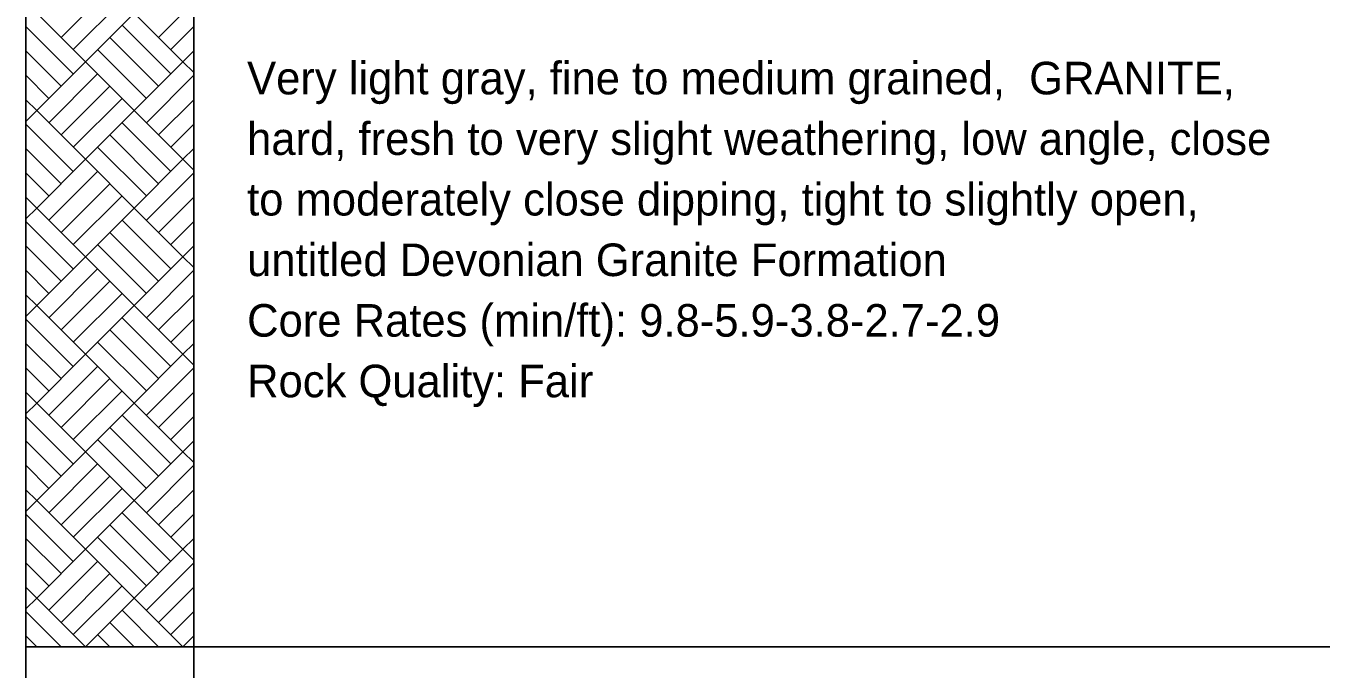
# Model space of a CAD drawing. Extents: x 9422 to 9552, y 6780 to 6860.
# Drawn here: x 9476.15 to 9485.01, y 6805.86 to 6810.26 of the extents above; entities that cross this region are included whole.
import ezdxf

# ---------------------------------------------------------------- set-up
doc = ezdxf.new("R2010")
doc.units = 0
doc.layers.add('7', color=7, linetype='Continuous')
doc.layers.add('8', color=7, linetype='Continuous')

msp = doc.modelspace()

# ---------------------------------------------------------------- linework, layer by layer
at = {"layer": '7'}
for p, q in [((9476.1476, 6811.0107), (9476.1476, 6806.0107)), ((9477.2959, 6806.0107), (9477.2959, 6811.0107)), ((9476.1476, 6806.0107), (9477.2959, 6806.0107))]:
    msp.add_line(p, q, dxfattribs=at)
for points in [[(9476.1476, 6822.0384), (9476.1476, 6796.9829)], [(9477.2959, 6822.0384), (9477.2959, 6796.9829)], [(9477.2959, 6806.0107), (9488.2385, 6806.0107)]]:
    msp.add_lwpolyline(points, dxfattribs=at)
at = {"layer": '8'}
for p, q in [((9476.7218, 6810.5107), (9476.3884, 6810.1773)), ((9476.8051, 6810.4273), (9476.4718, 6810.094)), ((9477.2959, 6810.4182), (9477.0551, 6810.1773)), ((9476.2218, 6810.344), (9476.5551, 6810.0107)), ((9476.8884, 6810.344), (9476.5551, 6810.0107)), ((9476.8884, 6810.344), (9476.5551, 6810.0107)), ((9476.8884, 6810.344), (9477.2218, 6810.0107)), ((9476.1476, 6810.2515), (9476.4718, 6809.9273)), ((9476.8051, 6810.2607), (9477.1384, 6809.9273)), ((9477.2959, 6810.2515), (9477.1384, 6810.094)), ((9476.7218, 6810.1773), (9477.0551, 6809.844)), ((9476.1476, 6810.0848), (9476.3884, 6809.844)), ((9476.6384, 6810.094), (9476.9718, 6809.7607)), ((9477.2959, 6810.0848), (9477.2218, 6810.0107)), ((9477.2959, 6810.0848), (9477.2218, 6810.0107)), ((9476.5551, 6810.0107), (9476.2218, 6809.6773)), ((9476.5551, 6810.0107), (9476.2218, 6809.6773)), ((9476.8884, 6809.6773), (9476.5551, 6810.0107)), ((9476.5551, 6810.0107), (9476.8884, 6809.6773)), ((9477.2218, 6810.0107), (9476.8884, 6809.6773)), ((9477.2218, 6810.0107), (9476.8884, 6809.6773)), ((9477.2959, 6809.9365), (9477.2218, 6810.0107)), ((9477.2218, 6810.0107), (9477.2959, 6809.9365)), ((9476.1476, 6809.9182), (9476.3051, 6809.7607)), ((9476.6384, 6809.9273), (9476.3051, 6809.594)), ((9477.2959, 6809.9182), (9476.9718, 6809.594)), ((9476.7218, 6809.844), (9476.3884, 6809.5107)), ((9476.2218, 6809.6773), (9476.1476, 6809.7515)), ((9476.8051, 6809.7607), (9476.4718, 6809.4273)), ((9477.2959, 6809.7515), (9477.0551, 6809.5107)), ((9476.2218, 6809.6773), (9476.1476, 6809.6032)), ((9476.2218, 6809.6773), (9476.5551, 6809.344)), ((9476.8884, 6809.6773), (9476.5551, 6809.344)), ((9476.8884, 6809.6773), (9476.5551, 6809.344)), ((9476.8884, 6809.6773), (9477.2218, 6809.344)), ((9476.1476, 6809.5848), (9476.4718, 6809.2607)), ((9476.8051, 6809.594), (9477.1384, 6809.2607)), ((9477.2959, 6809.5848), (9477.1384, 6809.4273)), ((9476.7218, 6809.5107), (9477.0551, 6809.1773)), ((9476.1476, 6809.4182), (9476.3884, 6809.1773)), ((9476.5551, 6809.344), (9476.2218, 6809.0107)), ((9476.5551, 6809.344), (9476.2218, 6809.0107)), ((9476.8884, 6809.0107), (9476.5551, 6809.344)), ((9476.5551, 6809.344), (9476.8884, 6809.0107)), ((9476.6384, 6809.4273), (9476.9718, 6809.094)), ((9477.2218, 6809.344), (9476.8884, 6809.0107)), ((9477.2218, 6809.344), (9476.8884, 6809.0107)), ((9477.2959, 6809.4182), (9477.2218, 6809.344)), ((9477.2959, 6809.4182), (9477.2218, 6809.344)), ((9477.2959, 6809.2699), (9477.2218, 6809.344)), ((9477.2218, 6809.344), (9477.2959, 6809.2699)), ((9476.6384, 6809.2607), (9476.3051, 6808.9273)), ((9476.1476, 6809.2515), (9476.3051, 6809.094)), ((9476.7218, 6809.1773), (9476.3884, 6808.844)), ((9477.2959, 6809.2515), (9476.9718, 6808.9273)), ((9476.2218, 6809.0107), (9476.1476, 6809.0848)), ((9476.8051, 6809.094), (9476.4718, 6808.7607)), ((9477.2959, 6809.0848), (9477.0551, 6808.844)), ((9476.2218, 6809.0107), (9476.1476, 6808.9365)), ((9476.2218, 6809.0107), (9476.5551, 6808.6773)), ((9476.8884, 6809.0107), (9476.5551, 6808.6773)), ((9476.8884, 6809.0107), (9476.5551, 6808.6773)), ((9476.8884, 6809.0107), (9477.2218, 6808.6773)), ((9476.1476, 6808.9182), (9476.4718, 6808.594)), ((9476.8051, 6808.9273), (9477.1384, 6808.594)), ((9477.2959, 6808.9182), (9477.1384, 6808.7607)), ((9476.7218, 6808.844), (9477.0551, 6808.5107)), ((9476.1476, 6808.7515), (9476.3884, 6808.5107)), ((9476.6384, 6808.7607), (9476.9718, 6808.4273)), ((9477.2959, 6808.7515), (9477.2218, 6808.6773)), ((9477.2959, 6808.7515), (9477.2218, 6808.6773)), ((9476.5551, 6808.6773), (9476.2218, 6808.344)), ((9476.5551, 6808.6773), (9476.2218, 6808.344)), ((9476.8884, 6808.344), (9476.5551, 6808.6773)), ((9476.5551, 6808.6773), (9476.8884, 6808.344)), ((9477.2218, 6808.6773), (9476.8884, 6808.344)), ((9477.2218, 6808.6773), (9476.8884, 6808.344)), ((9477.2959, 6808.6032), (9477.2218, 6808.6773)), ((9477.2218, 6808.6773), (9477.2959, 6808.6032)), ((9476.1476, 6808.5848), (9476.3051, 6808.4273)), ((9476.6384, 6808.594), (9476.3051, 6808.2607)), ((9477.2959, 6808.5848), (9476.9718, 6808.2607)), ((9476.7218, 6808.5107), (9476.3884, 6808.1773)), ((9476.2218, 6808.344), (9476.1476, 6808.4182)), ((9476.8051, 6808.4273), (9476.4718, 6808.094)), ((9477.2959, 6808.4182), (9477.0551, 6808.1773)), ((9476.2218, 6808.344), (9476.1476, 6808.2699)), ((9476.2218, 6808.344), (9476.5551, 6808.0107)), ((9476.8884, 6808.344), (9476.5551, 6808.0107)), ((9476.8884, 6808.344), (9476.5551, 6808.0107)), ((9476.8884, 6808.344), (9477.2218, 6808.0107)), ((9476.1476, 6808.2515), (9476.4718, 6807.9273)), ((9476.8051, 6808.2607), (9477.1384, 6807.9273)), ((9477.2959, 6808.2515), (9477.1384, 6808.094)), ((9476.7218, 6808.1773), (9477.0551, 6807.844)), ((9476.1476, 6808.0848), (9476.3884, 6807.844)), ((9476.6384, 6808.094), (9476.9718, 6807.7607)), ((9477.2959, 6808.0848), (9477.2218, 6808.0107)), ((9477.2959, 6808.0848), (9477.2218, 6808.0107)), ((9476.5551, 6808.0107), (9476.2218, 6807.6773)), ((9476.5551, 6808.0107), (9476.2218, 6807.6773)), ((9476.6384, 6807.9273), (9476.3051, 6807.594)), ((9476.8884, 6807.6773), (9476.5551, 6808.0107)), ((9476.5551, 6808.0107), (9476.8884, 6807.6773)), ((9477.2218, 6808.0107), (9476.8884, 6807.6773)), ((9477.2218, 6808.0107), (9476.8884, 6807.6773)), ((9477.2959, 6807.9365), (9477.2218, 6808.0107)), ((9477.2218, 6808.0107), (9477.2959, 6807.9365)), ((9476.1476, 6807.9182), (9476.3051, 6807.7607)), ((9476.7218, 6807.844), (9476.3884, 6807.5107)), ((9477.2959, 6807.9182), (9476.9718, 6807.594)), ((9476.2218, 6807.6773), (9476.1476, 6807.7515)), ((9476.8051, 6807.7607), (9476.4718, 6807.4273)), ((9477.2959, 6807.7515), (9477.0551, 6807.5107)), ((9476.2218, 6807.6773), (9476.1476, 6807.6032)), ((9476.2218, 6807.6773), (9476.5551, 6807.344)), ((9476.8884, 6807.6773), (9476.5551, 6807.344)), ((9476.8884, 6807.6773), (9476.5551, 6807.344)), ((9476.8884, 6807.6773), (9477.2218, 6807.344)), ((9476.1476, 6807.5848), (9476.4718, 6807.2607)), ((9476.8051, 6807.594), (9477.1384, 6807.2607)), ((9477.2959, 6807.5848), (9477.1384, 6807.4273)), ((9476.7218, 6807.5107), (9477.0551, 6807.1773)), ((9476.1476, 6807.4182), (9476.3884, 6807.1773)), ((9476.6384, 6807.4273), (9476.9718, 6807.094)), ((9477.2959, 6807.4182), (9477.2218, 6807.344)), ((9477.2959, 6807.4182), (9477.2218, 6807.344)), ((9476.5551, 6807.344), (9476.2218, 6807.0107)), ((9476.5551, 6807.344), (9476.2218, 6807.0107)), ((9476.8884, 6807.0107), (9476.5551, 6807.344)), ((9476.5551, 6807.344), (9476.8884, 6807.0107)), ((9477.2218, 6807.344), (9476.8884, 6807.0107)), ((9477.2218, 6807.344), (9476.8884, 6807.0107)), ((9477.2959, 6807.2699), (9477.2218, 6807.344)), ((9477.2218, 6807.344), (9477.2959, 6807.2699)), ((9476.1476, 6807.2515), (9476.3051, 6807.094)), ((9476.6384, 6807.2607), (9476.3051, 6806.9273)), ((9477.2959, 6807.2515), (9476.9718, 6806.9273)), ((9476.7218, 6807.1773), (9476.3884, 6806.844)), ((9476.2218, 6807.0107), (9476.1476, 6807.0848)), ((9476.8051, 6807.094), (9476.4718, 6806.7607)), ((9477.2959, 6807.0848), (9477.0551, 6806.844)), ((9476.2218, 6807.0107), (9476.1476, 6806.9365)), ((9476.2218, 6807.0107), (9476.5551, 6806.6773)), ((9476.8884, 6807.0107), (9476.5551, 6806.6773)), ((9476.8884, 6807.0107), (9476.5551, 6806.6773)), ((9476.8884, 6807.0107), (9477.2218, 6806.6773)), ((9476.1476, 6806.9182), (9476.4718, 6806.594)), ((9476.8051, 6806.9273), (9477.1384, 6806.594)), ((9477.2959, 6806.9182), (9477.1384, 6806.7607)), ((9476.7218, 6806.844), (9477.0551, 6806.5107)), ((9476.1476, 6806.7515), (9476.3884, 6806.5107)), ((9476.6384, 6806.7607), (9476.9718, 6806.4273)), ((9477.2959, 6806.7515), (9477.2218, 6806.6773)), ((9477.2959, 6806.7515), (9477.2218, 6806.6773)), ((9476.5551, 6806.6773), (9476.2218, 6806.344)), ((9476.5551, 6806.6773), (9476.2218, 6806.344)), ((9476.8884, 6806.344), (9476.5551, 6806.6773)), ((9476.5551, 6806.6773), (9476.8884, 6806.344)), ((9477.2218, 6806.6773), (9476.8884, 6806.344)), ((9477.2218, 6806.6773), (9476.8884, 6806.344)), ((9477.2959, 6806.6032), (9477.2218, 6806.6773)), ((9477.2218, 6806.6773), (9477.2959, 6806.6032)), ((9476.1476, 6806.5848), (9476.3051, 6806.4273)), ((9476.6384, 6806.594), (9476.3051, 6806.2607)), ((9476.7218, 6806.5107), (9476.3884, 6806.1773)), ((9477.2959, 6806.5848), (9476.9718, 6806.2607)), ((9476.8051, 6806.4273), (9476.4718, 6806.094)), ((9476.2218, 6806.344), (9476.1476, 6806.4182)), ((9476.2218, 6806.344), (9476.1476, 6806.2699)), ((9476.2218, 6806.344), (9476.5551, 6806.0107)), ((9476.8884, 6806.344), (9476.5551, 6806.0107)), ((9476.8884, 6806.344), (9476.5551, 6806.0107)), ((9476.8884, 6806.344), (9477.2218, 6806.0107)), ((9477.2959, 6806.4182), (9477.0551, 6806.1773)), ((9476.1476, 6806.2515), (9476.3884, 6806.0107)), ((9476.8051, 6806.2607), (9477.0551, 6806.0107)), ((9477.2959, 6806.2515), (9477.1384, 6806.094)), ((9476.7218, 6806.1773), (9476.8884, 6806.0107)), ((9476.1476, 6806.0848), (9476.2218, 6806.0107)), ((9476.6384, 6806.094), (9476.7218, 6806.0107)), ((9477.2959, 6806.0848), (9477.2218, 6806.0107)), ((9477.2959, 6806.0848), (9477.2218, 6806.0107)), ((9476.5551, 6806.0107), (9476.5551, 6806.0107)), ((9476.5551, 6806.0107), (9476.5551, 6806.0107)), ((9476.5551, 6806.0107), (9476.5551, 6806.0107)), ((9476.5551, 6806.0107), (9476.5551, 6806.0107)), ((9477.2218, 6806.0107), (9477.2218, 6806.0107)), ((9477.2218, 6806.0107), (9477.2218, 6806.0107)), ((9477.2218, 6806.0107), (9477.2218, 6806.0107)), ((9477.2218, 6806.0107), (9477.2218, 6806.0107))]:
    msp.add_line(p, q, dxfattribs=at)

# ---------------------------------------------------------------- texts
at = {"layer": '7'}
for s, p in [('Very light gray, fine to medium grained,  GRANITE,', (9477.6605, 6809.7879)), ('hard, fresh to very slight weathering, low angle, close', (9477.6605, 6809.3737)), ('to moderately close dipping, tight to slightly open,', (9477.6605, 6808.9595)), ('untitled Devonian Granite Formation', (9477.6605, 6808.5453)), ('Core Rates (min/ft): 9.8-5.9-3.8-2.7-2.9', (9477.6605, 6808.1311)), ('Rock Quality: Fair', (9477.6605, 6807.7168))]:
    msp.add_text(s, height=0.2228, dxfattribs=at).set_placement(p)

doc.saveas('drawing.dxf')
